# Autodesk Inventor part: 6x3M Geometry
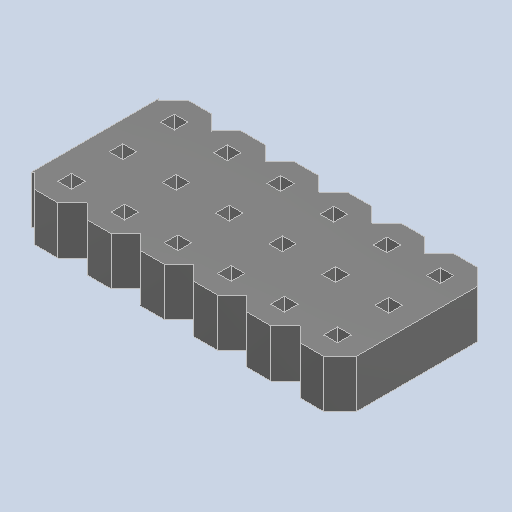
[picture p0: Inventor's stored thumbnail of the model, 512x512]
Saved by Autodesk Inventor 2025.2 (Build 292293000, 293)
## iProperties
Created: 2025-04
Part Number: 6x3M Geometry
Material: Generic
Description: PART-6x3M Geometry-DESC
Document SubType Name: Modeling
Designer: BennF
Density: 1 g/cm^3
Appearance: Default
Author: BennF
Revision Number: NONE
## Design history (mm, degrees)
feature "7"
body "Solid1"
